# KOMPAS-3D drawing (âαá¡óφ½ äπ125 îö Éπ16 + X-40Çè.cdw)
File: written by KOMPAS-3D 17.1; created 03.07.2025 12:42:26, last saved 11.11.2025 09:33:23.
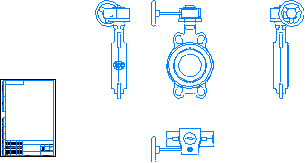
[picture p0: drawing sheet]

Sheet 1: A4, portrait

Title block, sheet 1: sheets: 1; sheet format: A4; stored path: \\adlc.lan\data\АДЛ_ПКД\3D-модели\ADL production\Дисковые поворотные затворы ГРАНВЭЛ\межфланцевый с китайским редуктором Ру16\KOMPAS 2D\Гранвэл Ду125 МФ Ру16 + X-40АК.cdw

Views: Вид 1, Спереди, Проекционный вид 2, Проекционный вид 3, Проекционный вид 4
Referenced files in \\adlc.lan\data\АДЛ_ПКД\3D-модели\ADL production\Дисковые поворотные затворы ГРАНВЭЛ\межфланцевый с китайским редуктором Ру16\KOMPAS 3D\: Гранвэл Ду125 МФ Ру16 + X-40АК.m3d
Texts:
  Andrey
  АДЛ
Dimensions and other numbers on the sheet: 1:1; 1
